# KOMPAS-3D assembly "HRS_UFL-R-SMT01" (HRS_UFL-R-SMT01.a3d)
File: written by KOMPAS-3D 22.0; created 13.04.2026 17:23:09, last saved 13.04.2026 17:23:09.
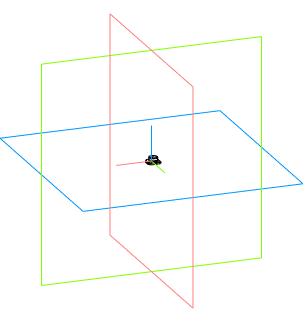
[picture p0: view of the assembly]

Document properties: Автор: Andrey; Полное имя файла: C:\Users\User1\Documents\HRS_UFL-R-SMT01.a3d

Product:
- Component [detail]: U.FL-R-SMT(01)  | qty 1  | source file: U.FL-R-SMT(01).m3d
- Part/product: HRS_UFL-R-SMT01
    Комментарий: HRS_UFL-R-SMT01

Referenced files in C:\Users\User1\Documents\: U.FL-R-SMT(01).m3d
